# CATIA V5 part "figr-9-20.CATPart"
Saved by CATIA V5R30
Part number: Part3
Bounding box of the stored display mesh (mm): x -112 to 0, y -101.683 to 100, z -80.304 to 44.415
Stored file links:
  D:\PROJECTS\CATIA V56R 2020\Resources\Parts File\c09_catia_v5_6r2020_prt\figr-9-20.CATPart
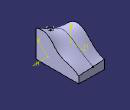
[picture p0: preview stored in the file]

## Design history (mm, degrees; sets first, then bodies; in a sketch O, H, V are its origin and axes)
Set1
  Plane1: type Offset, RefPlane yz-plane, Offset -112
  Plane2: type Offset, RefPlane yz-plane, Offset -63
  Plane3: type Normal, Curve Sketch4, RefPoint vertex of Sketch4
Body1 (main body)
  Sketch1 on yz-plane, origin (0, 0, 0), H (0, 1, 0), V (0, 0, 1)
    spline S1 through (-92.6897, 40.1119) (-30, 30) (10, -10) (60, -30) (97.3103, -50.3041)
    line L1 (97.3103, -50.3041) -> (97.3103, -80.3041)
    line L2 (97.3103, -80.3041) -> (-92.6897, -80.3041)
    line L3 (-92.6897, -80.3041) -> (-92.6897, 40.1119)
    point P3 (-92.6897, 40.1119)
    point P4 (97.3103, -50.3041)
    point P5 (-92.6897, 40.1119)
    point P6 (97.3103, -50.3041)
    vertical: L1 V, L3 V
    horizontal: L2 H
    coincidence: P5 P3, P6 P4
  Sketch2 on Plane1, origin (-112, 0, 0), H (0, 1, 0), V (0, 0, 1)
    spline S1 through (-90, -30) (-70, 10) (-20, 40) (40, 0) (100, -40)
    line L1 (100, -40) -> (100, -80)
    line L2 (100, -80) -> (-90, -80)
    line L3 (-90, -80) -> (-90, -30)
    point P3 (-90, -30)
    point P4 (100, -40)
    point P5 (40, 0)
    point P6 (-90, -30)
    point P7 (100, -40)
    coincidence: P5 H, P6 P3, P7 P4
    vertical: L1 V, L3 V
    horizontal: L2 H
  Loft1: Sections (Sketch1; Sketch2)
  Sketch3 on Plane3, origin (0, -40.1726, -44.9298), H (1, 0, 0), V (0, -0.7455, 0.6665)
    point P1 (-63, 68.4187)
    line L1 (-63, 68.4187) -> (-75.2117, 62.4925)
    line L2 (-75.2117, 62.4925) -> (-79.6266, 71.5898)
    line L3 (-79.6266, 71.5898) -> (-57.1205, 82.5119)
    line L4 (-57.1205, 82.5119) -> (-52.7056, 73.4145)
    point P5 (-52.7056, 73.4145)
    line L5 (-52.7056, 73.4145) -> (-63, 68.4187)
    reference projected point E1 (-63, 68.4187) from vertex of Sketch4
    perpendicularity: L2 L1
    parallelism: L3 L1, L4 L2, L5 L1
    coincidence: P5 L1, P1 E1
  Sketch4 on Plane2, origin (-63, 0, 0), H (0, 1, 0), V (0, 0, 1)
    intersected curve E1 from face of Loft1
